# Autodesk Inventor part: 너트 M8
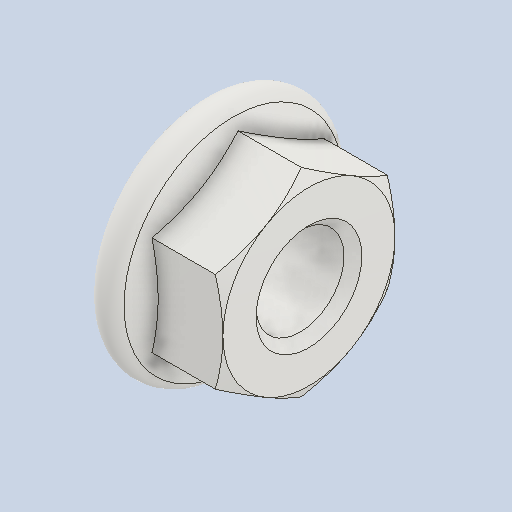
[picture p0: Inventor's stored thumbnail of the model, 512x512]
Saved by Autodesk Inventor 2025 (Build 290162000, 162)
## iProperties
Created: 2024-07
Part Number: 너트 M8
Material: 스테인리스강
Description: 플랜지붙이 6각 너트 - 일반 스레드
Document SubType Name: Modeling
Designer: Administrator
Density: 8 g/cm^3
Appearance: 기본값
Author: jhkim
Sending System: Autodesk Inventor 2025
Preprocessor: ST-DEVELOPER v20
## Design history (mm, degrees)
feature "Solid1"
node "솔리드1"
